Omron CX-Programmer project NewProject (CX-Programmer 6.11)

# PLC Elevator: CPM1(CPM1A) CPU20

## Global symbols (name address type ; comment)
Button_1 200.07 BOOL  ; Call Button 1st
Button_2 200.06 BOOL  ; Call Button 2nd
Button_3 200.05 BOOL  ; Call Button 3rd
Button_4 200.04 BOOL  ; Call Button 4th
Button_Dn 200.09 BOOL  ; Manual Down
Button_Up 200.08 BOOL  ; Manual Up
Fault_Initialize 211.00 BOOL  ; Fault - Initialize
Fault_Motor_Down 211.02 BOOL  ; Fault - Motor Down
Fault_Motor_Up 211.01 BOOL  ; Fault - Motor Up
Fault_Reset_Bit 208.00 BOOL  ; Fault Reset Bit
Floor_Number 220 CHANNEL  ; Current Floor Number
HMI_Step DM0 CHANNEL  ; HMI Step String
I_00 0.00 BOOL  ; GN Start - 4th
I_01 0.01 BOOL  ; BK Start - 3rd
I_02 0.02 BOOL  ; BK Jog - 2nd
I_03 0.03 BOOL  ; RD EStop - 1st
I_04 0.04 BOOL  ; RD Stop - UP
I_05 0.05 BOOL  ; RD Stop - DN
I_07 0.07 BOOL  ; Basement
I_08 0.08 BOOL  ; Level 1
I_09 0.09 BOOL  ; Level 4
I_10 0.10 BOOL  ; Level 3
I_11 0.11 BOOL  ; Level 2
LS_Basement 200.10 BOOL  ; Elevator @ Basement
LS_Level1 200.00 BOOL  ; Elevator @ Level 1
LS_Level2 200.01 BOOL  ; Elevator @ Level 2
LS_Level3 200.02 BOOL  ; Elevator @ Level 3
LS_Level4 200.03 BOOL  ; Elevator @ Level 4
O_01 10.01 BOOL  ; Up Motor
O_02 10.02 BOOL  ; Down Motor
Req_Floor 221 CHANNEL  ; Request Floor
Run_Motor_Down_15 210.03 BOOL  ; Run Down Motor (S15)
Run_Motor_Down_2 210.01 BOOL  ; Run Down Motor (S2)
Run_Motor_Down_30 210.05 BOOL  ; Run Down Motor (S30)
Run_Motor_Up_12 210.00 BOOL  ; Run Up Motor (S12)
Run_Motor_Up_20 210.02 BOOL  ; Run Up Motor (S20)
S_02 202.00 BOOL  ; Step S02
S_03A 202.01 BOOL  ; Step S03A
S_03B 202.02 BOOL  ; Step S03B
S_03C 202.03 BOOL  ; Step S03C
S_03D 202.04 BOOL  ; Step S03D
S_03E 202.05 BOOL  ; Step S03E
S_10 202.06 BOOL  ; Step S10
S_11 202.07 BOOL  ; Step S11
S_12 202.08 BOOL  ; Step S12
S_12A 202.09 BOOL  ; Step S12A
S_12B 202.10 BOOL  ; Step S12B
S_12C 202.11 BOOL  ; Step S12C
S_12D 202.12 BOOL  ; Step S12D
S_15 204.05 BOOL  ; Step S15
S_15A 204.06 BOOL  ; Step S15A
S_15B 204.07 BOOL  ; Step S15B
S_15C 204.08 BOOL  ; Step S15C
S_15D 204.09 BOOL  ; Step S15D
S_20 204.02 BOOL  ; Step S20
S_30 204.03 BOOL  ; Step S30
S_60 206.00 BOOL  ; Initialize Fault Timer
S_65 206.01 BOOL  ; Motor Up Fault Timer
S_70 206.02 BOOL  ; Motor Down Fault Timer
S_75 206.03 BOOL  ; Manual Up Fault Timer
S_80 206.04 BOOL  ; Manual Down Fault Timer
T_00 201.00 BOOL  ; Transition T00
T_02A 201.01 BOOL  ; Transition T02A
T_02B 201.02 BOOL  ; Transition T02B
T_02C 201.03 BOOL  ; Transition T02C
T_02D 201.04 BOOL  ; Transition T02D
T_02E 201.05 BOOL  ; Transition T02E
T_02F 201.06 BOOL  ; Transition T02F
T_03A 201.07 BOOL  ; Transition T03A
T_03B 201.08 BOOL  ; Transition T03B
T_03C 201.09 BOOL  ; Transition T03C
T_03D 201.10 BOOL  ; Transition T03D
T_03E 201.11 BOOL  ; Transition T03E
T_10A 203.00 BOOL  ; Transition T10A
T_10B 203.01 BOOL  ; Transition T10B
T_10C 203.02 BOOL  ; Transition T10C
T_11A 203.03 BOOL  ; Transition T11A
T_11B 203.04 BOOL  ; Transition T11B
T_12 203.05 BOOL  ; Transition T12
T_12A 203.06 BOOL  ; Transition T12A
T_12A1 203.07 BOOL  ; Transition T12A1
T_12B 203.08 BOOL  ; Transition T12B
T_12B1 203.09 BOOL  ; Transition T12B1
T_12C 203.10 BOOL  ; Transition T12C
T_12C1 203.11 BOOL  ; Transition T12C1
T_12D 203.12 BOOL  ; Transition T12D
T_12D1 203.13 BOOL  ; Transition T12D1
T_12E 203.14 BOOL  ; Transition T12E
T_15 209.00 BOOL  ; Transition T15
T_15A 209.01 BOOL  ; Transition T15A
T_15A1 209.02 BOOL  ; Transition T15A1
T_15B 209.03 BOOL  ; Transition T15B
T_15B1 209.04 BOOL  ; Transition T15B1
T_15C 209.05 BOOL  ; Transition T15C
T_15C1 209.06 BOOL  ; Transition T15C1
T_15D 209.07 BOOL  ; Transition T15D
T_15D1 209.08 BOOL  ; Transition T15D1
T_15E 209.09 BOOL  ; Transition T15E
T_20A 205.00 BOOL  ; Transition T20A
T_20B 205.01 BOOL  ; Transition T20B
T_20C 205.02 BOOL  ; Transition T20C
T_20D 205.03 BOOL  ; Transition T20D
T_20E 205.04 BOOL  ; Transition T20E
T_30A 205.05 BOOL  ; Transition T30A
T_30B 205.06 BOOL  ; Transition T30B
T_30C 205.07 BOOL  ; Transition T30C
T_30D 205.08 BOOL  ; Transition T30D
T_30E 205.09 BOOL  ; Transition T30E
T_60 207.00 BOOL  ; Transition T60
T_65 207.01 BOOL  ; Transition T65
T_70 207.02 BOOL  ; Transition T70
T_75 207.03 BOOL  ; Transition T75
T_80 207.04 BOOL  ; Transition T80
Timer_Flt_Dn TIM003 BOOL  ; Motor Down Fault
Timer_Flt_Init TIM001 BOOL  ; Initialization Fault Timer
Timer_Flt_Man_Down TIM006 BOOL  ; Manual Down Fault
Timer_Flt_Man_Up TIM004 BOOL  ; Manual Up Fault
Timer_Flt_Up TIM002 BOOL  ; Motor Up Fault
Timer_Running20 TIM005 BOOL  ; Running Timer (S20)
Timer_Running30 TIM007 BOOL  ; Running Timer (S30)

## Program Elevator (no task)

### Section Transistions

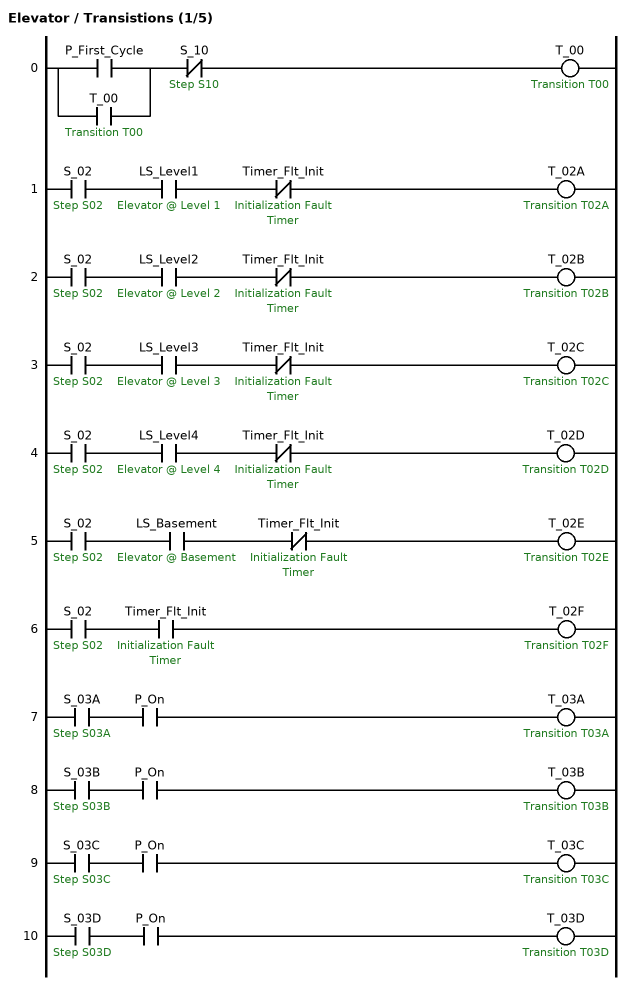
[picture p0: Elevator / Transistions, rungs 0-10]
; rung 0
LD P_First_Cycle
OR T_00  ; Transition T00
ANDNOT S_10  ; Step S10
OUT T_00  ; Transition T00
; rung 1
LD S_02  ; Step S02
AND LS_Level1  ; Elevator @ Level 1
ANDNOT Timer_Flt_Init  ; Initialization Fault Timer
OUT T_02A  ; Transition T02A
; rung 2
LD S_02  ; Step S02
AND LS_Level2  ; Elevator @ Level 2
ANDNOT Timer_Flt_Init  ; Initialization Fault Timer
OUT T_02B  ; Transition T02B
; rung 3
LD S_02  ; Step S02
AND LS_Level3  ; Elevator @ Level 3
ANDNOT Timer_Flt_Init  ; Initialization Fault Timer
OUT T_02C  ; Transition T02C
; rung 4
LD S_02  ; Step S02
AND LS_Level4  ; Elevator @ Level 4
ANDNOT Timer_Flt_Init  ; Initialization Fault Timer
OUT T_02D  ; Transition T02D
; rung 5
LD S_02  ; Step S02
AND LS_Basement  ; Elevator @ Basement
ANDNOT Timer_Flt_Init  ; Initialization Fault Timer
OUT T_02E  ; Transition T02E
; rung 6
LD S_02  ; Step S02
AND Timer_Flt_Init  ; Initialization Fault Timer
OUT T_02F  ; Transition T02F
; rung 7
LD S_03A  ; Step S03A
AND P_On
OUT T_03A  ; Transition T03A
; rung 8
LD S_03B  ; Step S03B
AND P_On
OUT T_03B  ; Transition T03B
; rung 9
LD S_03C  ; Step S03C
AND P_On
OUT T_03C  ; Transition T03C
; rung 10
LD S_03D  ; Step S03D
AND P_On
OUT T_03D  ; Transition T03D

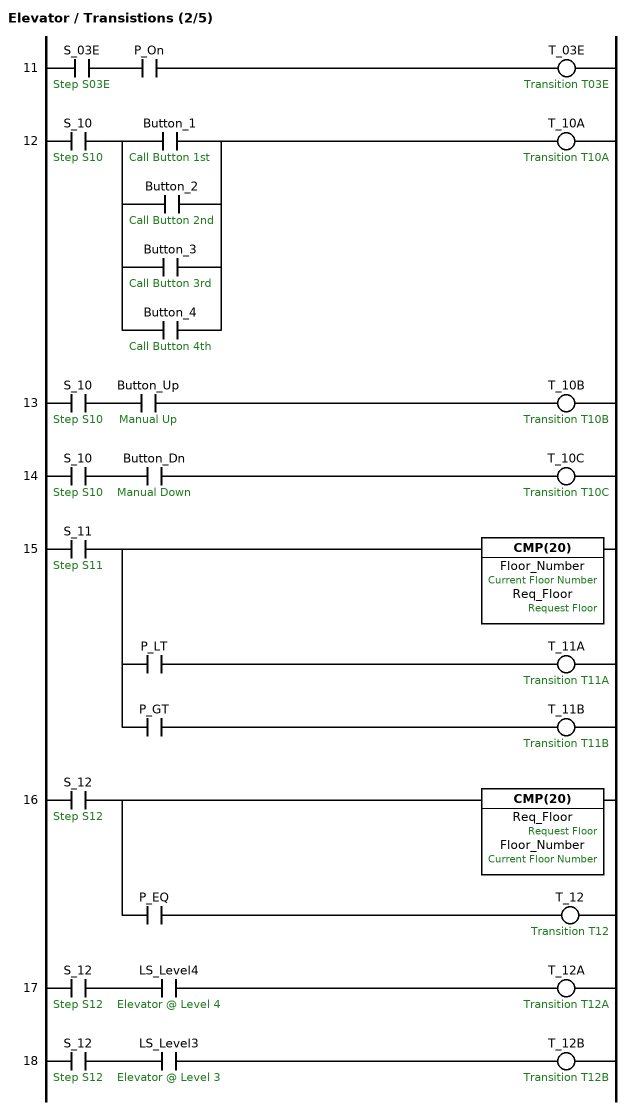
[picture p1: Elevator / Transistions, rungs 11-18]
; rung 11
LD S_03E  ; Step S03E
AND P_On
OUT T_03E  ; Transition T03E
; rung 12
LD S_10  ; Step S10
LD Button_1  ; Call Button 1st
OR Button_2  ; Call Button 2nd
OR Button_3  ; Call Button 3rd
OR Button_4  ; Call Button 4th
ANDLD
OUT T_10A  ; Transition T10A
; rung 13
LD S_10  ; Step S10
AND Button_Up  ; Manual Up
OUT T_10B  ; Transition T10B
; rung 14
LD S_10  ; Step S10
AND Button_Dn  ; Manual Down
OUT T_10C  ; Transition T10C
; rung 15
LD S_11  ; Step S11
OUT TR0
CMP(20) Floor_Number Req_Floor  ; Current Floor Number, Request Floor
AND P_LT
OUT T_11A  ; Transition T11A
LD TR0
AND P_GT
OUT T_11B  ; Transition T11B
; rung 16
LD S_12  ; Step S12
CMP(20) Req_Floor Floor_Number  ; Request Floor, Current Floor Number
AND P_EQ
OUT T_12  ; Transition T12
; rung 17
LD S_12  ; Step S12
AND LS_Level4  ; Elevator @ Level 4
OUT T_12A  ; Transition T12A
; rung 18
LD S_12  ; Step S12
AND LS_Level3  ; Elevator @ Level 3
OUT T_12B  ; Transition T12B

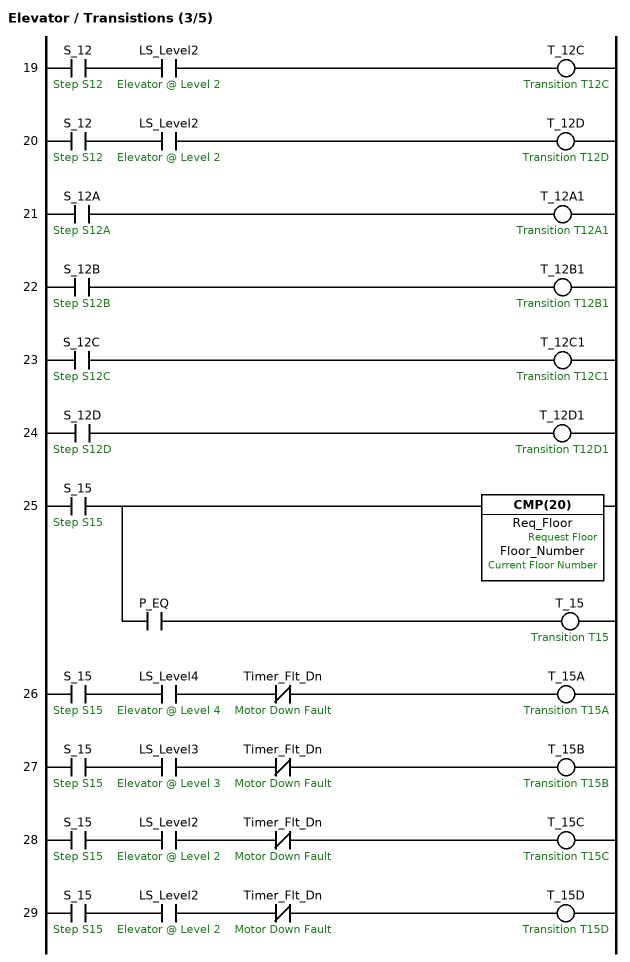
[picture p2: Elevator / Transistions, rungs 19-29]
; rung 19
LD S_12  ; Step S12
AND LS_Level2  ; Elevator @ Level 2
OUT T_12C  ; Transition T12C
; rung 20
LD S_12  ; Step S12
AND LS_Level2  ; Elevator @ Level 2
OUT T_12D  ; Transition T12D
; rung 21
LD S_12A  ; Step S12A
OUT T_12A1  ; Transition T12A1
; rung 22
LD S_12B  ; Step S12B
OUT T_12B1  ; Transition T12B1
; rung 23
LD S_12C  ; Step S12C
OUT T_12C1  ; Transition T12C1
; rung 24
LD S_12D  ; Step S12D
OUT T_12D1  ; Transition T12D1
; rung 25
LD S_15  ; Step S15
CMP(20) Req_Floor Floor_Number  ; Request Floor, Current Floor Number
AND P_EQ
OUT T_15  ; Transition T15
; rung 26
LD S_15  ; Step S15
AND LS_Level4  ; Elevator @ Level 4
ANDNOT Timer_Flt_Dn  ; Motor Down Fault
OUT T_15A  ; Transition T15A
; rung 27
LD S_15  ; Step S15
AND LS_Level3  ; Elevator @ Level 3
ANDNOT Timer_Flt_Dn  ; Motor Down Fault
OUT T_15B  ; Transition T15B
; rung 28
LD S_15  ; Step S15
AND LS_Level2  ; Elevator @ Level 2
ANDNOT Timer_Flt_Dn  ; Motor Down Fault
OUT T_15C  ; Transition T15C
; rung 29
LD S_15  ; Step S15
AND LS_Level2  ; Elevator @ Level 2
ANDNOT Timer_Flt_Dn  ; Motor Down Fault
OUT T_15D  ; Transition T15D

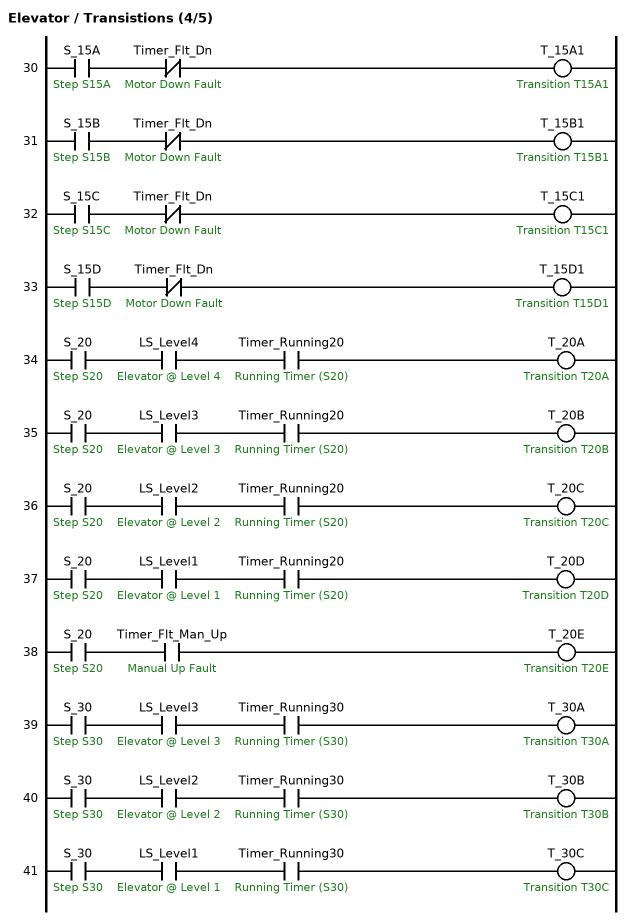
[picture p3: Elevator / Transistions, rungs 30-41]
; rung 30
LD S_15A  ; Step S15A
ANDNOT Timer_Flt_Dn  ; Motor Down Fault
OUT T_15A1  ; Transition T15A1
; rung 31
LD S_15B  ; Step S15B
ANDNOT Timer_Flt_Dn  ; Motor Down Fault
OUT T_15B1  ; Transition T15B1
; rung 32
LD S_15C  ; Step S15C
ANDNOT Timer_Flt_Dn  ; Motor Down Fault
OUT T_15C1  ; Transition T15C1
; rung 33
LD S_15D  ; Step S15D
ANDNOT Timer_Flt_Dn  ; Motor Down Fault
OUT T_15D1  ; Transition T15D1
; rung 34
LD S_20  ; Step S20
AND LS_Level4  ; Elevator @ Level 4
AND Timer_Running20  ; Running Timer (S20)
OUT T_20A  ; Transition T20A
; rung 35
LD S_20  ; Step S20
AND LS_Level3  ; Elevator @ Level 3
AND Timer_Running20  ; Running Timer (S20)
OUT T_20B  ; Transition T20B
; rung 36
LD S_20  ; Step S20
AND LS_Level2  ; Elevator @ Level 2
AND Timer_Running20  ; Running Timer (S20)
OUT T_20C  ; Transition T20C
; rung 37
LD S_20  ; Step S20
AND LS_Level1  ; Elevator @ Level 1
AND Timer_Running20  ; Running Timer (S20)
OUT T_20D  ; Transition T20D
; rung 38
LD S_20  ; Step S20
AND Timer_Flt_Man_Up  ; Manual Up Fault
OUT T_20E  ; Transition T20E
; rung 39
LD S_30  ; Step S30
AND LS_Level3  ; Elevator @ Level 3
AND Timer_Running30  ; Running Timer (S30)
OUT T_30A  ; Transition T30A
; rung 40
LD S_30  ; Step S30
AND LS_Level2  ; Elevator @ Level 2
AND Timer_Running30  ; Running Timer (S30)
OUT T_30B  ; Transition T30B
; rung 41
LD S_30  ; Step S30
AND LS_Level1  ; Elevator @ Level 1
AND Timer_Running30  ; Running Timer (S30)
OUT T_30C  ; Transition T30C

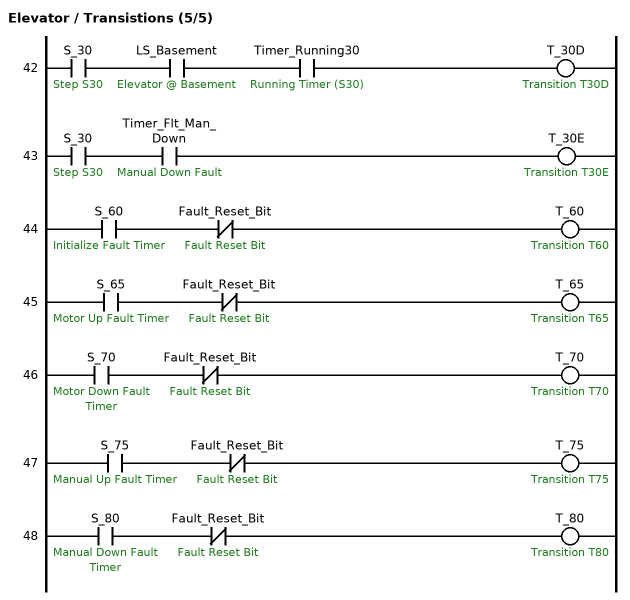
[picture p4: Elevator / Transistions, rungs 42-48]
; rung 42
LD S_30  ; Step S30
AND LS_Basement  ; Elevator @ Basement
AND Timer_Running30  ; Running Timer (S30)
OUT T_30D  ; Transition T30D
; rung 43
LD S_30  ; Step S30
AND Timer_Flt_Man_Down  ; Manual Down Fault
OUT T_30E  ; Transition T30E
; rung 44
LD S_60  ; Initialize Fault Timer
ANDNOT Fault_Reset_Bit  ; Fault Reset Bit
OUT T_60  ; Transition T60
; rung 45
LD S_65  ; Motor Up Fault Timer
ANDNOT Fault_Reset_Bit  ; Fault Reset Bit
OUT T_65  ; Transition T65
; rung 46
LD S_70  ; Motor Down Fault Timer
ANDNOT Fault_Reset_Bit  ; Fault Reset Bit
OUT T_70  ; Transition T70
; rung 47
LD S_75  ; Manual Up Fault Timer
ANDNOT Fault_Reset_Bit  ; Fault Reset Bit
OUT T_75  ; Transition T75
; rung 48
LD S_80  ; Manual Down Fault Timer
ANDNOT Fault_Reset_Bit  ; Fault Reset Bit
OUT T_80  ; Transition T80

### Section StepIterator

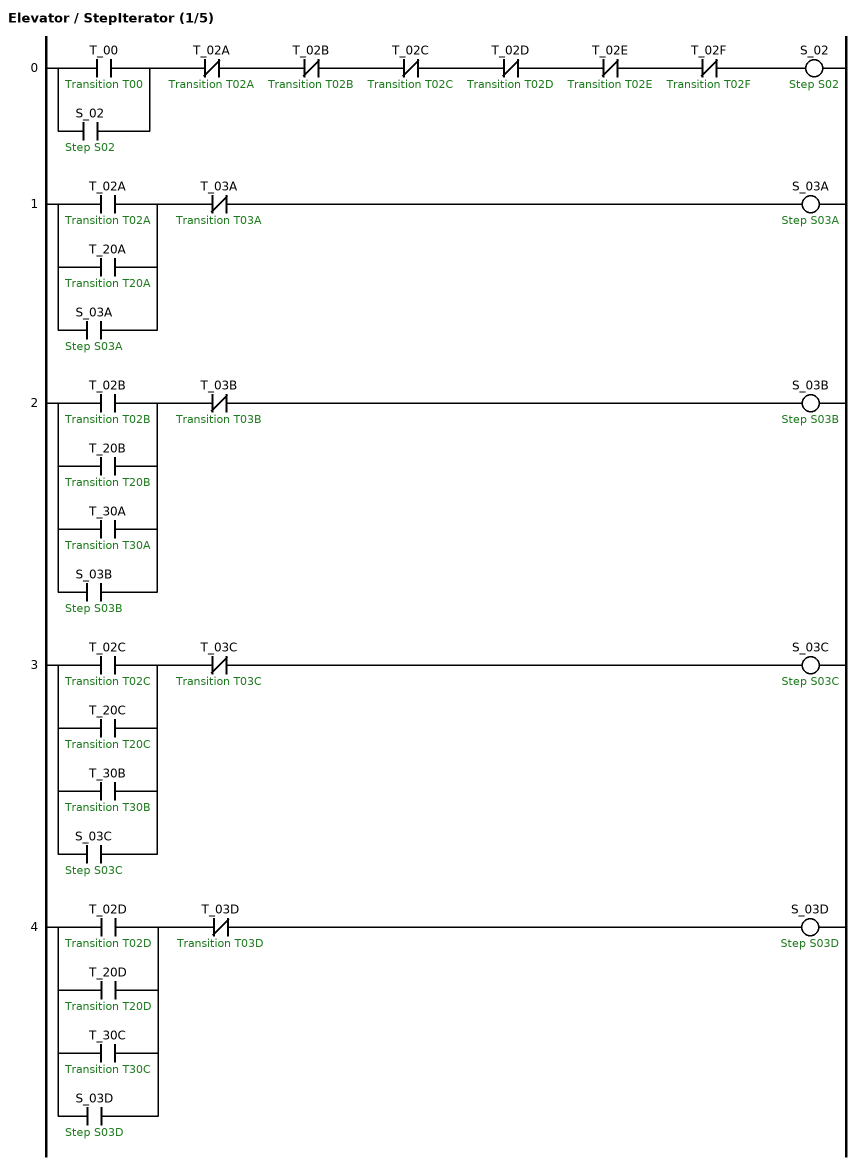
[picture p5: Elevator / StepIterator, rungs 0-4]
; rung 0
LD T_00  ; Transition T00
OR S_02  ; Step S02
ANDNOT T_02A  ; Transition T02A
ANDNOT T_02B  ; Transition T02B
ANDNOT T_02C  ; Transition T02C
ANDNOT T_02D  ; Transition T02D
ANDNOT T_02E  ; Transition T02E
ANDNOT T_02F  ; Transition T02F
OUT S_02  ; Step S02
; rung 1
LD T_02A  ; Transition T02A
OR T_20A  ; Transition T20A
OR S_03A  ; Step S03A
ANDNOT T_03A  ; Transition T03A
OUT S_03A  ; Step S03A
; rung 2
LD T_02B  ; Transition T02B
OR T_20B  ; Transition T20B
OR T_30A  ; Transition T30A
OR S_03B  ; Step S03B
ANDNOT T_03B  ; Transition T03B
OUT S_03B  ; Step S03B
; rung 3
LD T_02C  ; Transition T02C
OR T_20C  ; Transition T20C
OR T_30B  ; Transition T30B
OR S_03C  ; Step S03C
ANDNOT T_03C  ; Transition T03C
OUT S_03C  ; Step S03C
; rung 4
LD T_02D  ; Transition T02D
OR T_20D  ; Transition T20D
OR T_30C  ; Transition T30C
OR S_03D  ; Step S03D
ANDNOT T_03D  ; Transition T03D
OUT S_03D  ; Step S03D

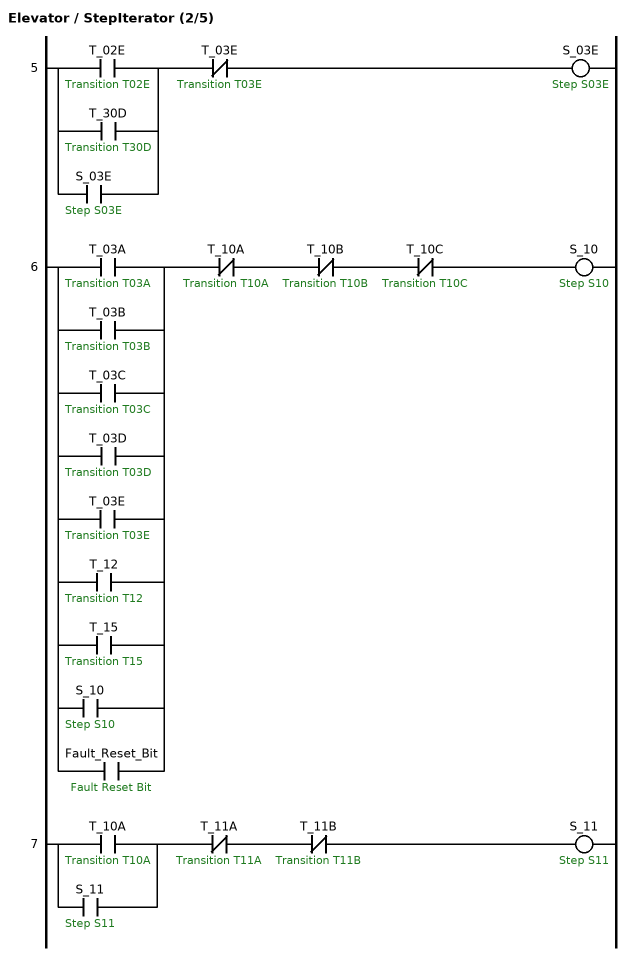
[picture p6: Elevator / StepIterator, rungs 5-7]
; rung 5
LD T_02E  ; Transition T02E
OR T_30D  ; Transition T30D
OR S_03E  ; Step S03E
ANDNOT T_03E  ; Transition T03E
OUT S_03E  ; Step S03E
; rung 6
LD T_03A  ; Transition T03A
OR T_03B  ; Transition T03B
OR T_03C  ; Transition T03C
OR T_03D  ; Transition T03D
OR T_03E  ; Transition T03E
OR T_12  ; Transition T12
OR T_15  ; Transition T15
OR S_10  ; Step S10
OR Fault_Reset_Bit  ; Fault Reset Bit
ANDNOT T_10A  ; Transition T10A
ANDNOT T_10B  ; Transition T10B
ANDNOT T_10C  ; Transition T10C
OUT S_10  ; Step S10
; rung 7
LD T_10A  ; Transition T10A
OR S_11  ; Step S11
ANDNOT T_11A  ; Transition T11A
ANDNOT T_11B  ; Transition T11B
OUT S_11  ; Step S11

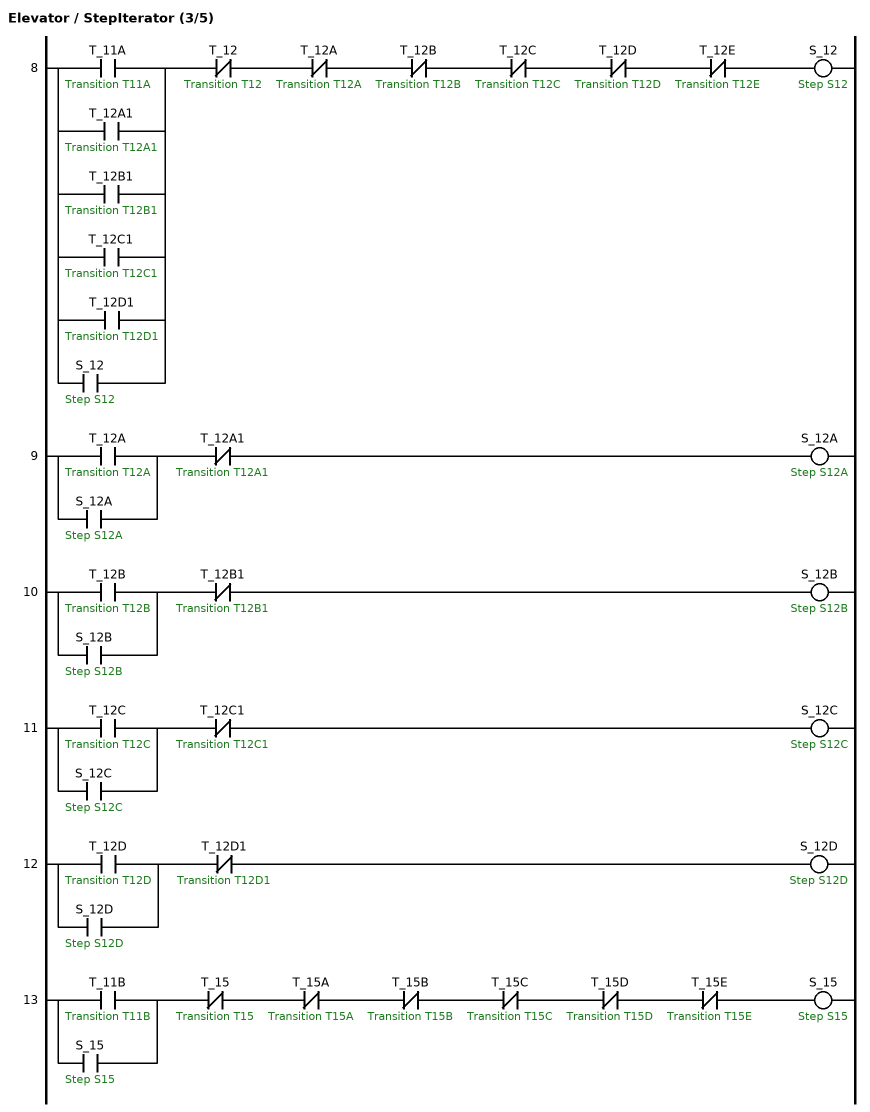
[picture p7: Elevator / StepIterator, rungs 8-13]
; rung 8
LD T_11A  ; Transition T11A
OR T_12A1  ; Transition T12A1
OR T_12B1  ; Transition T12B1
OR T_12C1  ; Transition T12C1
OR T_12D1  ; Transition T12D1
OR S_12  ; Step S12
ANDNOT T_12  ; Transition T12
ANDNOT T_12A  ; Transition T12A
ANDNOT T_12B  ; Transition T12B
ANDNOT T_12C  ; Transition T12C
ANDNOT T_12D  ; Transition T12D
ANDNOT T_12E  ; Transition T12E
OUT S_12  ; Step S12
; rung 9
LD T_12A  ; Transition T12A
OR S_12A  ; Step S12A
ANDNOT T_12A1  ; Transition T12A1
OUT S_12A  ; Step S12A
; rung 10
LD T_12B  ; Transition T12B
OR S_12B  ; Step S12B
ANDNOT T_12B1  ; Transition T12B1
OUT S_12B  ; Step S12B
; rung 11
LD T_12C  ; Transition T12C
OR S_12C  ; Step S12C
ANDNOT T_12C1  ; Transition T12C1
OUT S_12C  ; Step S12C
; rung 12
LD T_12D  ; Transition T12D
OR S_12D  ; Step S12D
ANDNOT T_12D1  ; Transition T12D1
OUT S_12D  ; Step S12D
; rung 13
LD T_11B  ; Transition T11B
OR S_15  ; Step S15
ANDNOT T_15  ; Transition T15
ANDNOT T_15A  ; Transition T15A
ANDNOT T_15B  ; Transition T15B
ANDNOT T_15C  ; Transition T15C
ANDNOT T_15D  ; Transition T15D
ANDNOT T_15E  ; Transition T15E
OUT S_15  ; Step S15

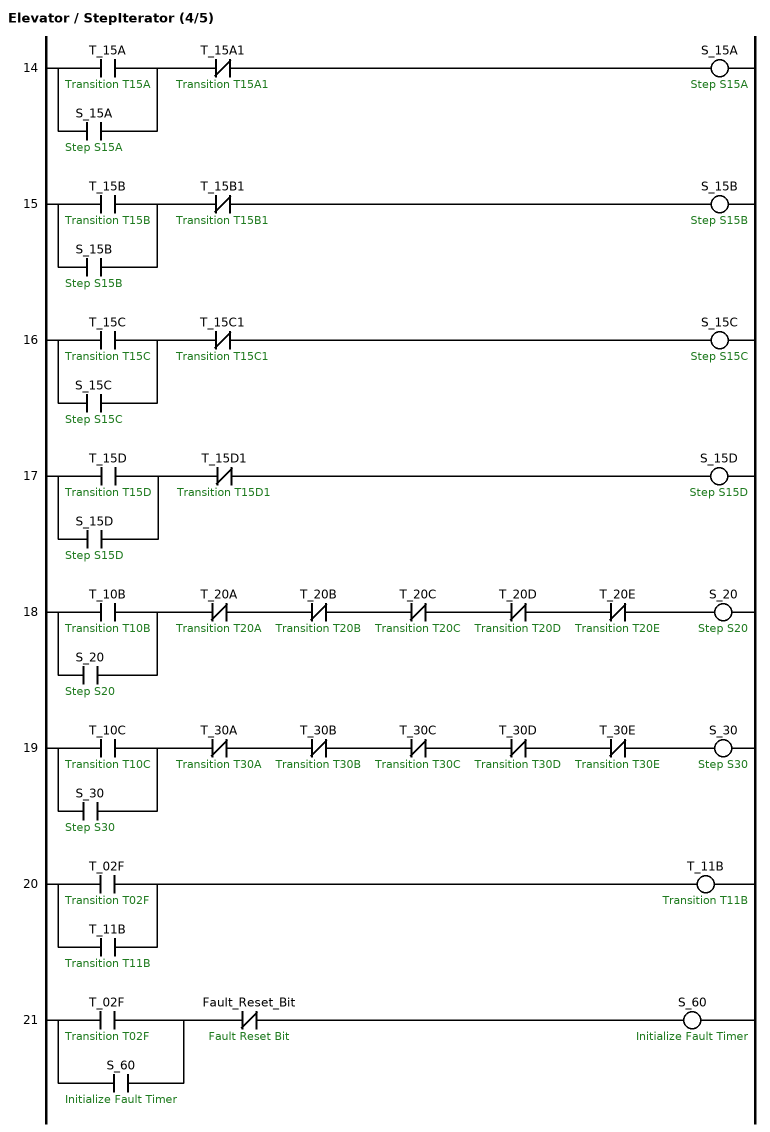
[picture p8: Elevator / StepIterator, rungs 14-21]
; rung 14
LD T_15A  ; Transition T15A
OR S_15A  ; Step S15A
ANDNOT T_15A1  ; Transition T15A1
OUT S_15A  ; Step S15A
; rung 15
LD T_15B  ; Transition T15B
OR S_15B  ; Step S15B
ANDNOT T_15B1  ; Transition T15B1
OUT S_15B  ; Step S15B
; rung 16
LD T_15C  ; Transition T15C
OR S_15C  ; Step S15C
ANDNOT T_15C1  ; Transition T15C1
OUT S_15C  ; Step S15C
; rung 17
LD T_15D  ; Transition T15D
OR S_15D  ; Step S15D
ANDNOT T_15D1  ; Transition T15D1
OUT S_15D  ; Step S15D
; rung 18
LD T_10B  ; Transition T10B
OR S_20  ; Step S20
ANDNOT T_20A  ; Transition T20A
ANDNOT T_20B  ; Transition T20B
ANDNOT T_20C  ; Transition T20C
ANDNOT T_20D  ; Transition T20D
ANDNOT T_20E  ; Transition T20E
OUT S_20  ; Step S20
; rung 19
LD T_10C  ; Transition T10C
OR S_30  ; Step S30
ANDNOT T_30A  ; Transition T30A
ANDNOT T_30B  ; Transition T30B
ANDNOT T_30C  ; Transition T30C
ANDNOT T_30D  ; Transition T30D
ANDNOT T_30E  ; Transition T30E
OUT S_30  ; Step S30
; rung 20
LD T_02F  ; Transition T02F
OR T_11B  ; Transition T11B
OUT T_11B  ; Transition T11B
; rung 21
LD T_02F  ; Transition T02F
OR S_60  ; Initialize Fault Timer
ANDNOT Fault_Reset_Bit  ; Fault Reset Bit
OUT S_60  ; Initialize Fault Timer

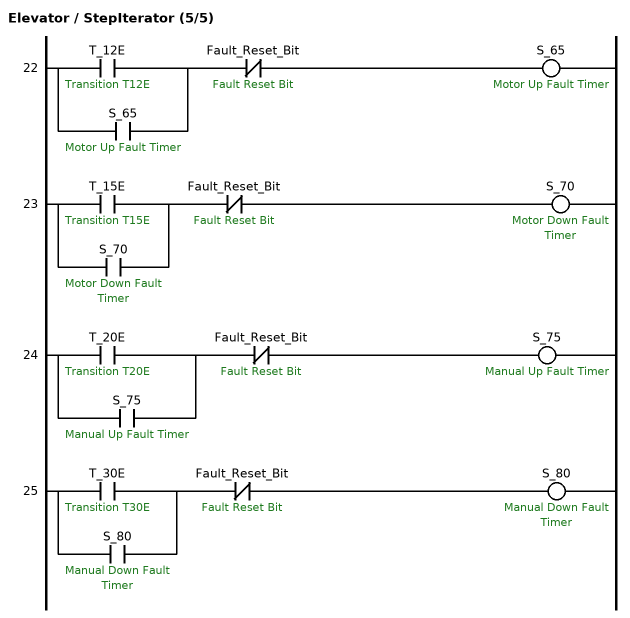
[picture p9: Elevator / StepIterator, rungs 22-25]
; rung 22
LD T_12E  ; Transition T12E
OR S_65  ; Motor Up Fault Timer
ANDNOT Fault_Reset_Bit  ; Fault Reset Bit
OUT S_65  ; Motor Up Fault Timer
; rung 23
LD T_15E  ; Transition T15E
OR S_70  ; Motor Down Fault Timer
ANDNOT Fault_Reset_Bit  ; Fault Reset Bit
OUT S_70  ; Motor Down Fault Timer
; rung 24
LD T_20E  ; Transition T20E
OR S_75  ; Manual Up Fault Timer
ANDNOT Fault_Reset_Bit  ; Fault Reset Bit
OUT S_75  ; Manual Up Fault Timer
; rung 25
LD T_30E  ; Transition T30E
OR S_80  ; Manual Down Fault Timer
ANDNOT Fault_Reset_Bit  ; Fault Reset Bit
OUT S_80  ; Manual Down Fault Timer

### Section Steps

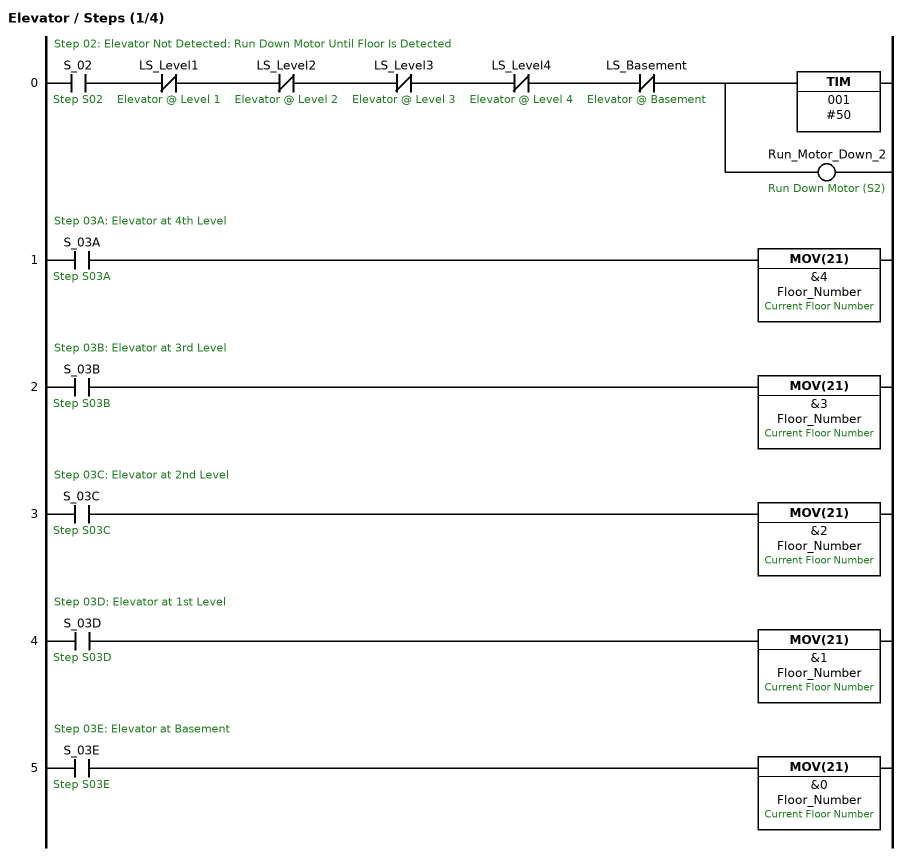
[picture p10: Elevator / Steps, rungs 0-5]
; rung 0: Step 02: Elevator Not Detected: Run Down Motor Until Floor Is Detected
LD S_02  ; Step S02
ANDNOT LS_Level1  ; Elevator @ Level 1
ANDNOT LS_Level2  ; Elevator @ Level 2
ANDNOT LS_Level3  ; Elevator @ Level 3
ANDNOT LS_Level4  ; Elevator @ Level 4
ANDNOT LS_Basement  ; Elevator @ Basement
TIM 001 #50
OUT Run_Motor_Down_2  ; Run Down Motor (S2)
; rung 1: Step 03A: Elevator at 4th Level
LD S_03A  ; Step S03A
MOV(21) &4 Floor_Number  ; Current Floor Number
; rung 2: Step 03B: Elevator at 3rd Level
LD S_03B  ; Step S03B
MOV(21) &3 Floor_Number  ; Current Floor Number
; rung 3: Step 03C: Elevator at 2nd Level
LD S_03C  ; Step S03C
MOV(21) &2 Floor_Number  ; Current Floor Number
; rung 4: Step 03D: Elevator at 1st Level
LD S_03D  ; Step S03D
MOV(21) &1 Floor_Number  ; Current Floor Number
; rung 5: Step 03E: Elevator at Basement
LD S_03E  ; Step S03E
MOV(21) &0 Floor_Number  ; Current Floor Number
; rung 6: Step 10: Wait for Call

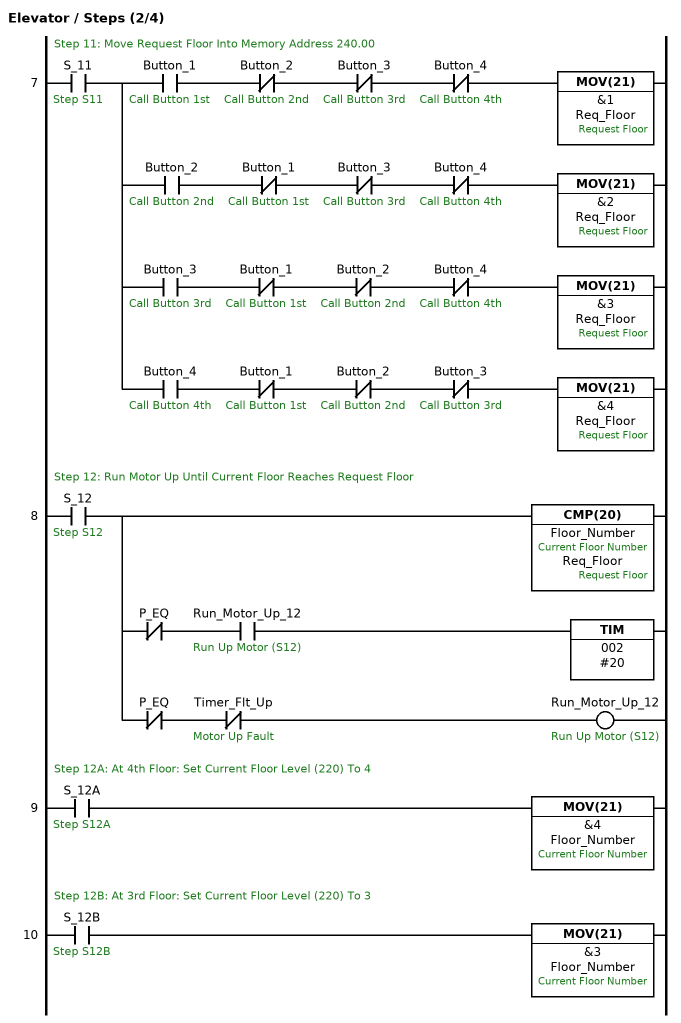
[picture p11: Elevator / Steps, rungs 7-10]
; rung 7: Step 11: Move Request Floor Into Memory Address 240.00
LD S_11  ; Step S11
OUT TR0
AND Button_1  ; Call Button 1st
ANDNOT Button_2  ; Call Button 2nd
ANDNOT Button_3  ; Call Button 3rd
ANDNOT Button_4  ; Call Button 4th
MOV(21) &1 Req_Floor  ; Request Floor
LD TR0
AND Button_2  ; Call Button 2nd
ANDNOT Button_1  ; Call Button 1st
ANDNOT Button_3  ; Call Button 3rd
ANDNOT Button_4  ; Call Button 4th
MOV(21) &2 Req_Floor  ; Request Floor
LD TR0
AND Button_3  ; Call Button 3rd
ANDNOT Button_1  ; Call Button 1st
ANDNOT Button_2  ; Call Button 2nd
ANDNOT Button_4  ; Call Button 4th
MOV(21) &3 Req_Floor  ; Request Floor
LD TR0
AND Button_4  ; Call Button 4th
ANDNOT Button_1  ; Call Button 1st
ANDNOT Button_2  ; Call Button 2nd
ANDNOT Button_3  ; Call Button 3rd
MOV(21) &4 Req_Floor  ; Request Floor
; rung 8: Step 12: Run Motor Up Until Current Floor Reaches Request Floor
LD S_12  ; Step S12
OUT TR0
CMP(20) Floor_Number Req_Floor  ; Current Floor Number, Request Floor
ANDNOT P_EQ
AND Run_Motor_Up_12  ; Run Up Motor (S12)
TIM 002 #20
LD TR0
ANDNOT P_EQ
ANDNOT Timer_Flt_Up  ; Motor Up Fault
OUT Run_Motor_Up_12  ; Run Up Motor (S12)
; rung 9: Step 12A: At 4th Floor: Set Current Floor Level (220) To 4
LD S_12A  ; Step S12A
MOV(21) &4 Floor_Number  ; Current Floor Number
; rung 10: Step 12B: At 3rd Floor: Set Current Floor Level (220) To 3
LD S_12B  ; Step S12B
MOV(21) &3 Floor_Number  ; Current Floor Number

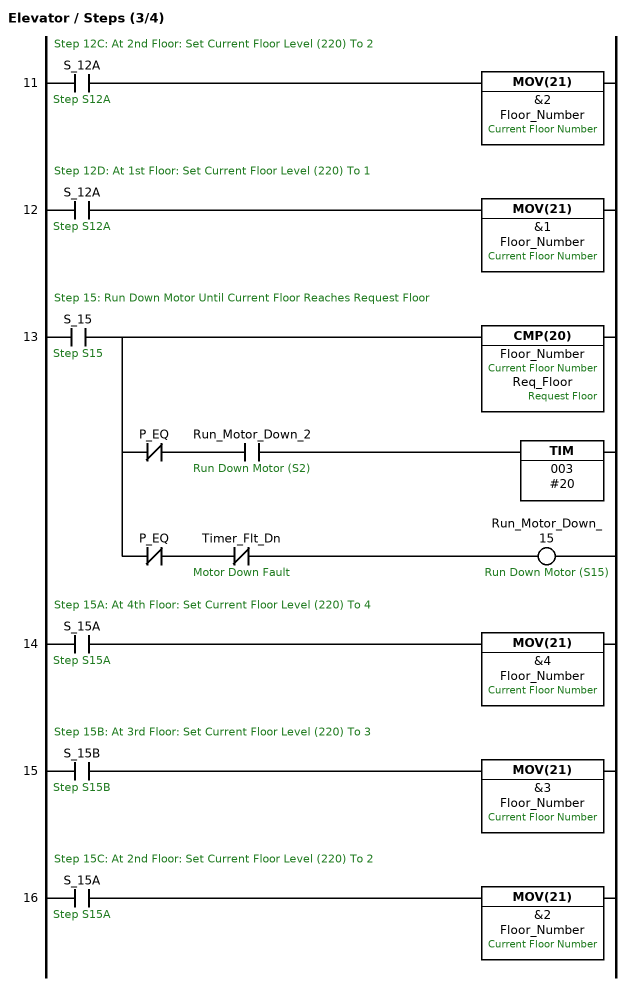
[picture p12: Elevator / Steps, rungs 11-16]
; rung 11: Step 12C: At 2nd Floor: Set Current Floor Level (220) To 2
LD S_12A  ; Step S12A
MOV(21) &2 Floor_Number  ; Current Floor Number
; rung 12: Step 12D: At 1st Floor: Set Current Floor Level (220) To 1
LD S_12A  ; Step S12A
MOV(21) &1 Floor_Number  ; Current Floor Number
; rung 13: Step 15: Run Down Motor Until Current Floor Reaches Request Floor
LD S_15  ; Step S15
OUT TR0
CMP(20) Floor_Number Req_Floor  ; Current Floor Number, Request Floor
ANDNOT P_EQ
AND Run_Motor_Down_2  ; Run Down Motor (S2)
TIM 003 #20
LD TR0
ANDNOT P_EQ
ANDNOT Timer_Flt_Dn  ; Motor Down Fault
OUT Run_Motor_Down_15  ; Run Down Motor (S15)
; rung 14: Step 15A: At 4th Floor: Set Current Floor Level (220) To 4
LD S_15A  ; Step S15A
MOV(21) &4 Floor_Number  ; Current Floor Number
; rung 15: Step 15B: At 3rd Floor: Set Current Floor Level (220) To 3
LD S_15B  ; Step S15B
MOV(21) &3 Floor_Number  ; Current Floor Number
; rung 16: Step 15C: At 2nd Floor: Set Current Floor Level (220) To 2
LD S_15A  ; Step S15A
MOV(21) &2 Floor_Number  ; Current Floor Number

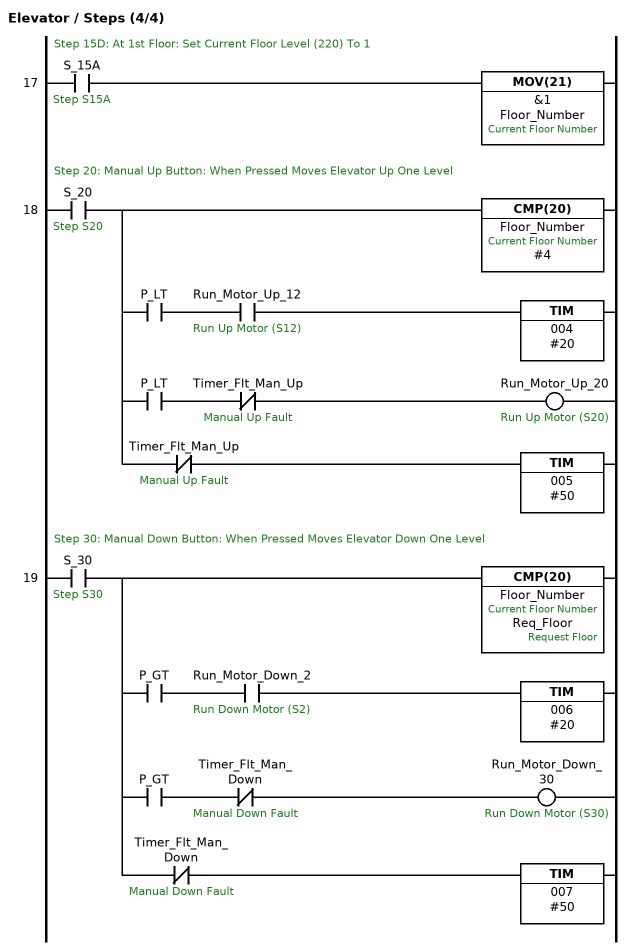
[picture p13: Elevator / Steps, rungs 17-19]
; rung 17: Step 15D: At 1st Floor: Set Current Floor Level (220) To 1
LD S_15A  ; Step S15A
MOV(21) &1 Floor_Number  ; Current Floor Number
; rung 18: Step 20: Manual Up Button: When Pressed Moves Elevator Up One Level
LD S_20  ; Step S20
OUT TR0
CMP(20) Floor_Number #4  ; Current Floor Number
AND P_LT
AND Run_Motor_Up_12  ; Run Up Motor (S12)
TIM 004 #20
LD TR0
AND P_LT
ANDNOT Timer_Flt_Man_Up  ; Manual Up Fault
OUT Run_Motor_Up_20  ; Run Up Motor (S20)
LD TR0
ANDNOT Timer_Flt_Man_Up  ; Manual Up Fault
TIM 005 #50
; rung 19: Step 30: Manual Down Button: When Pressed Moves Elevator Down One Level
LD S_30  ; Step S30
OUT TR0
CMP(20) Floor_Number Req_Floor  ; Current Floor Number, Request Floor
AND P_GT
AND Run_Motor_Down_2  ; Run Down Motor (S2)
TIM 006 #20
LD TR0
AND P_GT
ANDNOT Timer_Flt_Man_Down  ; Manual Down Fault
OUT Run_Motor_Down_30  ; Run Down Motor (S30)
LD TR0
ANDNOT Timer_Flt_Man_Down  ; Manual Down Fault
TIM 007 #50

### Section IO
; rung 1: Inputs

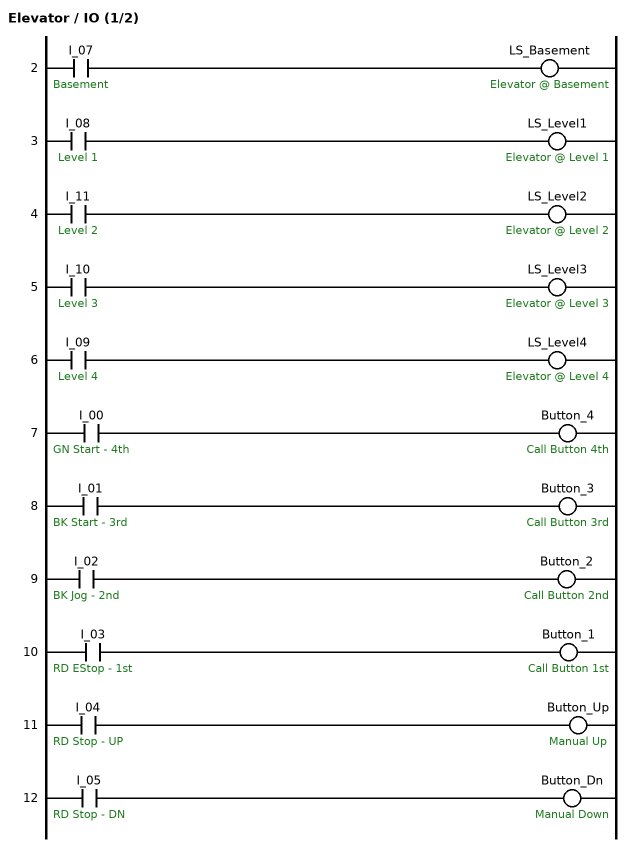
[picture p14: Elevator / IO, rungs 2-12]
; rung 2
LD I_07  ; Basement
OUT LS_Basement  ; Elevator @ Basement
; rung 3
LD I_08  ; Level 1
OUT LS_Level1  ; Elevator @ Level 1
; rung 4
LD I_11  ; Level 2
OUT LS_Level2  ; Elevator @ Level 2
; rung 5
LD I_10  ; Level 3
OUT LS_Level3  ; Elevator @ Level 3
; rung 6
LD I_09  ; Level 4
OUT LS_Level4  ; Elevator @ Level 4
; rung 7
LD I_00  ; GN Start - 4th
OUT Button_4  ; Call Button 4th
; rung 8
LD I_01  ; BK Start - 3rd
OUT Button_3  ; Call Button 3rd
; rung 9
LD I_02  ; BK Jog - 2nd
OUT Button_2  ; Call Button 2nd
; rung 10
LD I_03  ; RD EStop - 1st
OUT Button_1  ; Call Button 1st
; rung 11
LD I_04  ; RD Stop - UP
OUT Button_Up  ; Manual Up
; rung 12
LD I_05  ; RD Stop - DN
OUT Button_Dn  ; Manual Down
; rung 14: Outputs

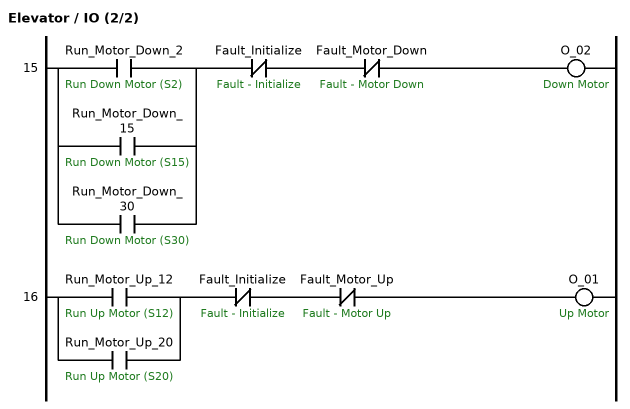
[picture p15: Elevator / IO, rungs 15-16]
; rung 15
LD Run_Motor_Down_2  ; Run Down Motor (S2)
OR Run_Motor_Down_15  ; Run Down Motor (S15)
OR Run_Motor_Down_30  ; Run Down Motor (S30)
ANDNOT Fault_Initialize  ; Fault - Initialize
ANDNOT Fault_Motor_Down  ; Fault - Motor Down
OUT O_02  ; Down Motor
; rung 16
LD Run_Motor_Up_12  ; Run Up Motor (S12)
OR Run_Motor_Up_20  ; Run Up Motor (S20)
ANDNOT Fault_Initialize  ; Fault - Initialize
ANDNOT Fault_Motor_Up  ; Fault - Motor Up
OUT O_01  ; Up Motor

### Section Faults

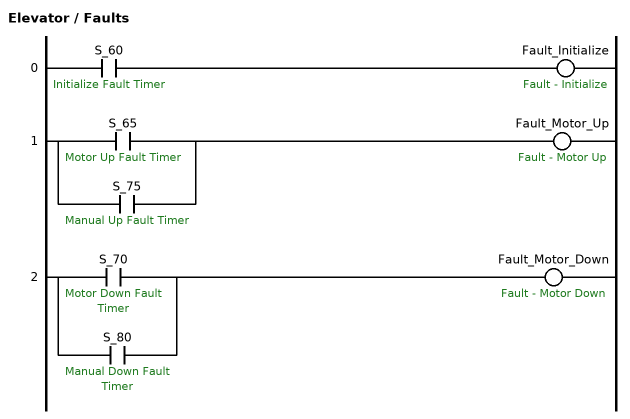
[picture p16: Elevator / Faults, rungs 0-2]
; rung 0
LD S_60  ; Initialize Fault Timer
OUT Fault_Initialize  ; Fault - Initialize
; rung 1
LD S_65  ; Motor Up Fault Timer
OR S_75  ; Manual Up Fault Timer
OUT Fault_Motor_Up  ; Fault - Motor Up
; rung 2
LD S_70  ; Motor Down Fault Timer
OR S_80  ; Manual Down Fault Timer
OUT Fault_Motor_Down  ; Fault - Motor Down

### Section HMI

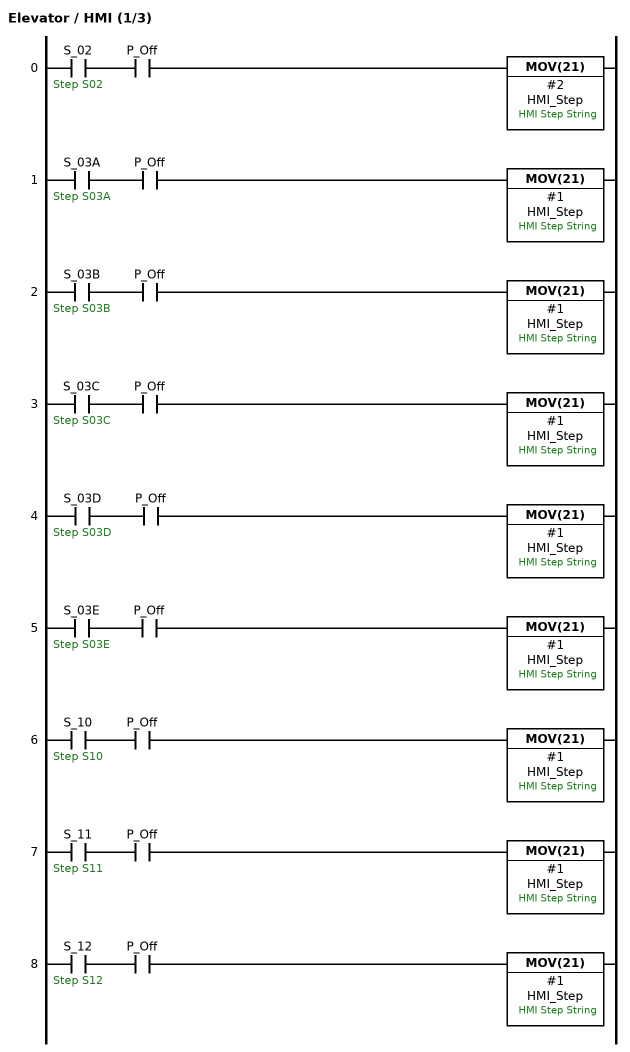
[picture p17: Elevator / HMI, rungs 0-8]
; rung 0
LD S_02  ; Step S02
AND P_Off
MOV(21) #2 HMI_Step  ; HMI Step String
; rung 1
LD S_03A  ; Step S03A
AND P_Off
MOV(21) #1 HMI_Step  ; HMI Step String
; rung 2
LD S_03B  ; Step S03B
AND P_Off
MOV(21) #1 HMI_Step  ; HMI Step String
; rung 3
LD S_03C  ; Step S03C
AND P_Off
MOV(21) #1 HMI_Step  ; HMI Step String
; rung 4
LD S_03D  ; Step S03D
AND P_Off
MOV(21) #1 HMI_Step  ; HMI Step String
; rung 5
LD S_03E  ; Step S03E
AND P_Off
MOV(21) #1 HMI_Step  ; HMI Step String
; rung 6
LD S_10  ; Step S10
AND P_Off
MOV(21) #1 HMI_Step  ; HMI Step String
; rung 7
LD S_11  ; Step S11
AND P_Off
MOV(21) #1 HMI_Step  ; HMI Step String
; rung 8
LD S_12  ; Step S12
AND P_Off
MOV(21) #1 HMI_Step  ; HMI Step String

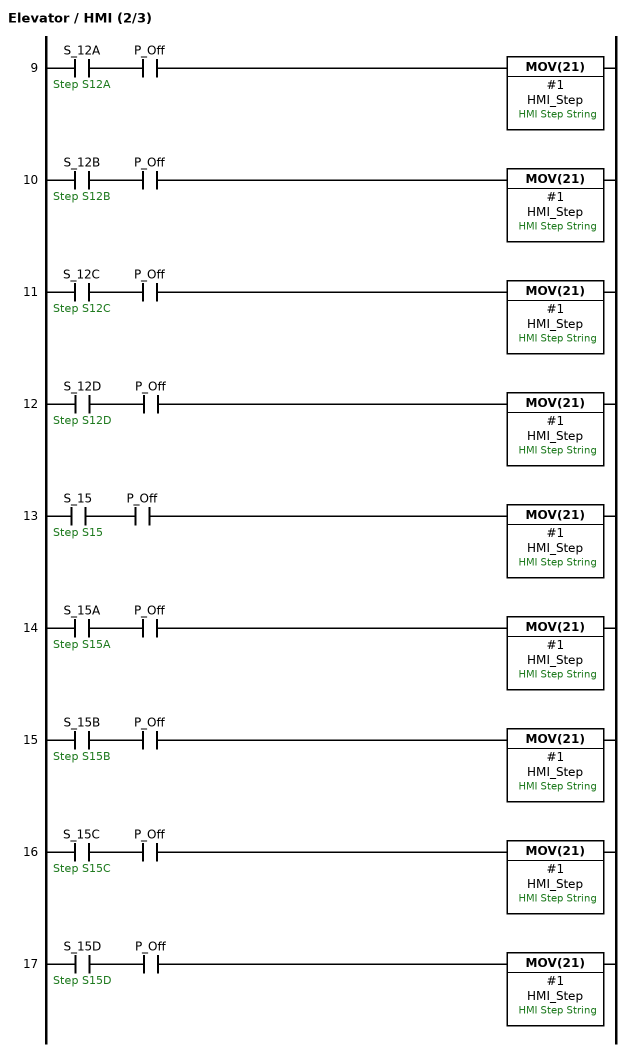
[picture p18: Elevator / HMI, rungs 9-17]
; rung 9
LD S_12A  ; Step S12A
AND P_Off
MOV(21) #1 HMI_Step  ; HMI Step String
; rung 10
LD S_12B  ; Step S12B
AND P_Off
MOV(21) #1 HMI_Step  ; HMI Step String
; rung 11
LD S_12C  ; Step S12C
AND P_Off
MOV(21) #1 HMI_Step  ; HMI Step String
; rung 12
LD S_12D  ; Step S12D
AND P_Off
MOV(21) #1 HMI_Step  ; HMI Step String
; rung 13
LD S_15  ; Step S15
AND P_Off
MOV(21) #1 HMI_Step  ; HMI Step String
; rung 14
LD S_15A  ; Step S15A
AND P_Off
MOV(21) #1 HMI_Step  ; HMI Step String
; rung 15
LD S_15B  ; Step S15B
AND P_Off
MOV(21) #1 HMI_Step  ; HMI Step String
; rung 16
LD S_15C  ; Step S15C
AND P_Off
MOV(21) #1 HMI_Step  ; HMI Step String
; rung 17
LD S_15D  ; Step S15D
AND P_Off
MOV(21) #1 HMI_Step  ; HMI Step String

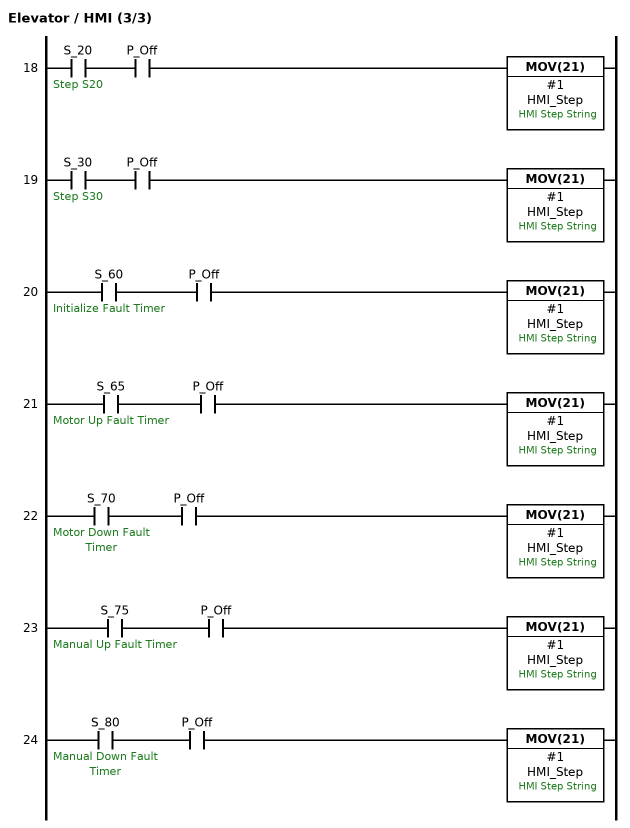
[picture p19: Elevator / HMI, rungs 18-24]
; rung 18
LD S_20  ; Step S20
AND P_Off
MOV(21) #1 HMI_Step  ; HMI Step String
; rung 19
LD S_30  ; Step S30
AND P_Off
MOV(21) #1 HMI_Step  ; HMI Step String
; rung 20
LD S_60  ; Initialize Fault Timer
AND P_Off
MOV(21) #1 HMI_Step  ; HMI Step String
; rung 21
LD S_65  ; Motor Up Fault Timer
AND P_Off
MOV(21) #1 HMI_Step  ; HMI Step String
; rung 22
LD S_70  ; Motor Down Fault Timer
AND P_Off
MOV(21) #1 HMI_Step  ; HMI Step String
; rung 23
LD S_75  ; Manual Up Fault Timer
AND P_Off
MOV(21) #1 HMI_Step  ; HMI Step String
; rung 24
LD S_80  ; Manual Down Fault Timer
AND P_Off
MOV(21) #1 HMI_Step  ; HMI Step String

### Section END
; rung 0
END(01)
